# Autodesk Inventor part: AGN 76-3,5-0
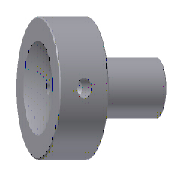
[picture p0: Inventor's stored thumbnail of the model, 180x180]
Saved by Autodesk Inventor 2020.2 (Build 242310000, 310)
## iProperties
Manager: www.cadconsulting.pl
Company: Fabian Stasiak CAD Consulting
Created: 2014-02
Part Number: AGN 76-3,5-0
Material: DIN 1.2312
Description: Sprue Bushing
Document SubType Name: Modeling
Designer: F.Stasiak
Standard Revision: 1
Manufacturer: DME
Language: pl-PL
Size Designation: 76-3,5-0
Categories: <MemberInstance><Categories><Category DisplayName="Forma wtryskowa" InternalName="349578f2-f4d4-4954-8c09-8e99297a61c0" Mnemonic="MOLD"><Category DisplayName="K
Density: 7.85 g/cm^3
Appearance: Domyślna
Catalog Web Link: www.expertbooks.pl
IsCustomPart: 1
Author: F.Stasiak
Subject: Zbiór ćwiczeń. Autodesk Inventor 2020. Kurs Professional
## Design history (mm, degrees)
sketch "Sketch1"
  geometry: L1 (0, -27.2)-(0, 23.2) reference; L2 (1.75, 20)-(19, 20); L3 (19, 20)-(19, 0); L4 (19, 0)-(12, 0); L5 (9, -3)-(9, -76); L6 (9, -76)-(4.264, -76); L7 (4.264, -76)-(1.75, 20); A1 r 3 centre (12, -3) between (12, 0) and (9, -3); 2 further points
  constraints: 12 end point, 3 parallel, 2 perpendicular, 2 point on circle, 2 point on line, 2 tangent, 1 centre point
  dimensions: "d0" = 18 diameter of L5 L1 (= D); "d3" = 38 diameter of L3 L1 (= d1); "d6" = 1.5 deg angle of L7 L1 (= 0.5 x Taper); "d7" = 20 distance between parallel lines of L4 L2 (= K_); "d8" = 76 distance between parallel lines of L4 L6 (= L); "d9" = 3 radius of A1 (= R3); "d62" = 3.5 diameter of point (1.75, 20) L1 (= d_); "d63" = 0 distance from line of point (1.75, 20) L2 (computed from Rd)
revolve "Revolution1" sketch "Sketch1" stored, may be unused: angle "d10" = 90 deg
sketch "Sketch2"
  geometry: L1 (0, -32.79)-(0, 56.739) reference; L2 (4.264, -76)-(1.75, 20) reference; L3 (-19, 20)-(19, 20) reference; L4 (0, 50.901)-(0, 19.901); A1 r 15.5 centre (0, 35.401) between (0, 19.901) and (0, 50.901); 2 further points
  constraints: 3 point on circle, 3 point on line, 2 end point, 1 centre point, 1 midpoint
  dimensions: "d64" = 0 distance from line of point (1.75, 20) L3 (computed from Rd); "d67" = 15.5 radius of A1 (= Rk)
revolve "Revolution2" sketch "Sketch2" stored, may be unused: angle "d13" = 90 deg
workplane "Work Plane1"
sketch "Sketch3"
  geometry: 2 further points
  constraints: 1 vertical alignment
  dimensions: "d43" = 10 distance of point (0, -10) point (0, 0) (= 0.5 x K_)
hole "Hole1" sketch "Sketch3" at (0, 0) diameter "d15" = 4 (= pd1); stored, may be unused: countersink angle "d19" = 90 deg, drill point angle "d21" = 118 deg; dims "d16" = 6, "d17" = 4, "d18" = 2, "d20" = 6 (= pl1)
chamfer "Chamfer1" distance "d22" = 0.3; stored, may be unused: second distance "d23" = 2, angle "d24" = 45 deg
sketch "Sketch4"
  geometry: L1 (0, -30.4)-(0, 42.4) reference; L2 (0, 40)-(19.5, 40); L3 (19.5, 40)-(19.5, 0); L4 (9, -76)-(0, -76); L5 (0, -76)-(0, 40); L6 (9, -3)-(9, -76); L7 (12, 0)-(19.5, 0); L8 (12, 0)-(9, -3); 2 further points
  constraints: 14 end point, 4 point on line, 2 horizontal, 2 parallel, 1 perpendicular, 1 vertical
  dimensions: "d56" = 3 distance of L7.start point (9, 0) (= R3_CS); "d57" = 3 distance of L6.start point (9, 0) (= d56); "d58" = 39 diameter of L3 L1 (= d1_CS); "d59" = 40 distance between parallel lines of L7 L2 (= K_CS); "d60" = 18 diameter of L6 L1 (= D_CS); "d61" = 76 distance between parallel lines of L7 L4 (= L_CS)
feature "RevolutionSrf1" sketch "Sketch4" dims angle "d33" = 90 deg
feature "Rzeźbienie1"
feature "Podział3"
feature "Podział5"
body "Solid1"
body "Srf1"
feature "Powierzchnia1"
body "Srf2"
other parameters: "L" = 76 [user parameter; used in 1 equation term], "d1" = 38 [user parameter; used in 1 equation term], "d_" = 3.5 [user parameter; used in 1 equation term], "D" = 18 [user parameter; used in 1 equation term], "K_" = 20 [user parameter; used in 2 equation terms], "R" = 0 [user parameter], "Taper" = 3 deg [user parameter; used in 1 equation term], "Rd" = 0 [user parameter; used in 2 equation terms], "R3" = 3 [user parameter; used in 1 equation term], "pd1" = 4 [user parameter; used in 1 equation term], "d1_CS" = 39 [user parameter; used in 1 equation term], "K_CS" = 40 [user parameter; used in 1 equation term], "d44" = 0, "d45" = 0, "d46" = 0, "L_CS" = 76 [user parameter; used in 1 equation term], "D_CS" = 18 [user parameter; used in 1 equation term], "pl1" = 6 [user parameter; used in 1 equation term], "R3_CS" = 3 [user parameter; used in 1 equation term], "Rk" = 15.5 [user parameter; used in 1 equation term]
